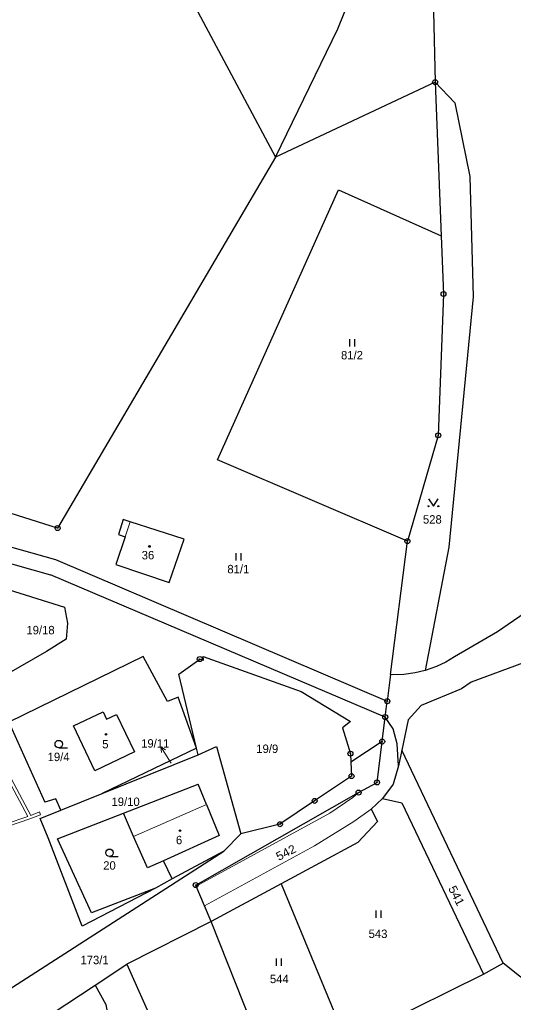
# Model space of a CAD drawing. Extents: x -653193 to -651624, y -1092017 to -1090260.
# Drawn here: x -652659.4 to -652559.8, y -1091313.6 to -1091115.4 of the extents above; entities that cross this region are included whole.
import ezdxf
from ezdxf.enums import TextEntityAlignment as Align

# ---------------------------------------------------------------- set-up
doc = ezdxf.new("R2010")
doc.units = 0
doc.header["$LTSCALE"] = 0.68
for name, color, linetype, lineweight in [('1', 7, 'Continuous', 25), ('13', 7, 'Continuous', 13), ('3', 7, 'Continuous', 25), ('4', 7, 'Continuous', 13), ('5', 7, 'Continuous', 25), ('7', 7, 'Continuous', 13), ('8', 7, 'Continuous', 25)]:
    doc.layers.add(name, color=color, linetype=linetype, lineweight=lineweight)
doc.layers.add('2', color=7, linetype='Continuous')

msp = doc.modelspace()

# ---------------------------------------------------------------- linework, layer by layer
at = {"layer": '1'}
for p, q in [((-652699, -1090972.63), (-652607.81, -1091143.07)), ((-652595.19, -1091117.19), (-652566.54, -1091045.56)), ((-652575.91, -1091113.74), (-652575.59, -1091127.97)), ((-652607.81, -1091143.07), (-652595.19, -1091117.19)), ((-652575.59, -1091127.97), (-652607.81, -1091143.07)), ((-652575.59, -1091127.97), (-652571.62, -1091132.16)), ((-652575.59, -1091127.97), (-652574.36, -1091158.97)), ((-652571.62, -1091132.16), (-652568.59, -1091146.97)), ((-652607.81, -1091143.07), (-652651.78, -1091217.9)), ((-652568.59, -1091146.97), (-652567.93, -1091171.28)), ((-652619.54, -1091204.12), (-652595.12, -1091149.69)), ((-652595.12, -1091149.69), (-652574.36, -1091158.97)), ((-652574.36, -1091158.97), (-652573.9, -1091170.7)), ((-652573.9, -1091170.7), (-652574.96, -1091199.2)), ((-652567.93, -1091171.28), (-652572.82, -1091221.74)), ((-652651.78, -1091217.9), (-652718.72, -1091196.81)), ((-652740.73, -1091199.19), (-652652.24, -1091224.26)), ((-652574.96, -1091199.2), (-652581.18, -1091220.54)), ((-652742.73, -1091201.93), (-652653.19, -1091227.34)), ((-652581.18, -1091220.54), (-652619.54, -1091204.12)), ((-652638.54, -1091216.14), (-652639.52, -1091219.18)), ((-652637.11, -1091216.61), (-652638.54, -1091216.14)), ((-652626.27, -1091220.15), (-652637.11, -1091216.61)), ((-652638.14, -1091219.64), (-652640.05, -1091225.25)), ((-652639.52, -1091219.18), (-652638.14, -1091219.64)), ((-652584.56, -1091247.44), (-652581.18, -1091220.54)), ((-652572.82, -1091221.74), (-652577.62, -1091246.64)), ((-652652.24, -1091224.26), (-652585.24, -1091252.83)), ((-652540.35, -1091223.27), (-652563.01, -1091238.81)), ((-652676.04, -1091225.83), (-652650.37, -1091233.85)), ((-652585.65, -1091256.02), (-652653.19, -1091227.34)), ((-652650.37, -1091233.85), (-652649.81, -1091237.05)), ((-652649.81, -1091237.05), (-652650.07, -1091240.31)), ((-652650.07, -1091240.31), (-652654.03, -1091242.76)), ((-652563.01, -1091238.81), (-652571.65, -1091243.87)), ((-652654.03, -1091242.76), (-652662.13, -1091247.41)), ((-652634.48, -1091243.82), (-652661.64, -1091257.02)), ((-652629.57, -1091252.89), (-652634.48, -1091243.82)), ((-652627.33, -1091247.39), (-652623.09, -1091244.32)), ((-652623.09, -1091244.32), (-652622.32, -1091244.57)), ((-652622.32, -1091244.57), (-652622.43, -1091243.83)), ((-652622.43, -1091243.83), (-652602.63, -1091250.88)), ((-652571.65, -1091243.87), (-652573.45, -1091244.94)), ((-652575.34, -1091245.82), (-652577.62, -1091246.64)), ((-652573.45, -1091244.94), (-652575.34, -1091245.82)), ((-652557.72, -1091245.07), (-652568.28, -1091248.96)), ((-652623.76, -1091262.29), (-652627.33, -1091247.39)), ((-652584.56, -1091247.44), (-652585.24, -1091252.83)), ((-652584.13, -1091247.52), (-652584.56, -1091247.44)), ((-652581.9, -1091247.44), (-652584.13, -1091247.52)), ((-652579.63, -1091247.12), (-652581.9, -1091247.44)), ((-652577.62, -1091246.64), (-652579.63, -1091247.12)), ((-652570.26, -1091250.29), (-652578.42, -1091253.66)), ((-652568.28, -1091248.96), (-652570.26, -1091250.29)), ((-652627.46, -1091251.99), (-652629.57, -1091252.89)), ((-652623.76, -1091262.29), (-652627.46, -1091251.99)), ((-652602.63, -1091250.88), (-652592.67, -1091256.93)), ((-652585.65, -1091256.02), (-652585.24, -1091252.83)), ((-652578.42, -1091253.66), (-652581.03, -1091256.58)), ((-652648.56, -1091257.78), (-652642.62, -1091254.96)), ((-652642.62, -1091254.96), (-652641.91, -1091256.46)), ((-652641.91, -1091256.46), (-652639.87, -1091255.49)), ((-652639.87, -1091255.49), (-652636.29, -1091263.04)), ((-652586.27, -1091260.95), (-652585.65, -1091256.02)), ((-652584.03, -1091258.36), (-652585.65, -1091256.02)), ((-652661.64, -1091257.02), (-652654.35, -1091273.21)), ((-652644.26, -1091266.83), (-652648.56, -1091257.78)), ((-652592.67, -1091256.93), (-652594.3, -1091258.2)), ((-652594.3, -1091258.2), (-652592.68, -1091263.4)), ((-652583.23, -1091261.42), (-652584.03, -1091258.36)), ((-652581.03, -1091256.58), (-652582.33, -1091262.72)), ((-652623.76, -1091262.29), (-652642.77, -1091271.41)), ((-652623.43, -1091263.65), (-652623.76, -1091262.29)), ((-652623.43, -1091263.65), (-652619.72, -1091261.95)), ((-652619.72, -1091261.95), (-652614.79, -1091279.58)), ((-652586.27, -1091260.95), (-652592.6, -1091265.08)), ((-652587.31, -1091269.19), (-652586.27, -1091260.95)), ((-652583, -1091265.88), (-652583.23, -1091261.42)), ((-652636.29, -1091263.04), (-652644.26, -1091266.83)), ((-652642.77, -1091271.41), (-652623.43, -1091263.65)), ((-652592.68, -1091263.4), (-652592.6, -1091265.08)), ((-652582.33, -1091262.72), (-652583, -1091265.88)), ((-652561.87, -1091305.65), (-652582.33, -1091262.72)), ((-652592.6, -1091265.08), (-652592.45, -1091267.92)), ((-652583, -1091265.88), (-652584.07, -1091269.52)), ((-652592.45, -1091267.92), (-652599.9, -1091272.92)), ((-652621.72, -1091273.68), (-652623.38, -1091269.58)), ((-652591.03, -1091271.25), (-652587.31, -1091269.19)), ((-652584.07, -1091269.52), (-652586.24, -1091272.47)), ((-652651.12, -1091274.76), (-652642.77, -1091271.41)), ((-652623.91, -1091289.9), (-652591.03, -1091271.25)), ((-652652.13, -1091272.54), (-652654.35, -1091273.21)), ((-652651.12, -1091274.76), (-652652.13, -1091272.54)), ((-652621.72, -1091273.68), (-652619.16, -1091279.89)), ((-652599.9, -1091272.92), (-652606.9, -1091277.63)), ((-652586.24, -1091272.47), (-652588.5, -1091274.56)), ((-652586.24, -1091272.47), (-652582.31, -1091273.31)), ((-652582.31, -1091273.31), (-652565.79, -1091307.87)), ((-652655.33, -1091276.44), (-652651.12, -1091274.76)), ((-652636.46, -1091280.08), (-652638.49, -1091275.43)), ((-652588.5, -1091274.56), (-652587.21, -1091277.07)), ((-652653.7, -1091280.37), (-652655.33, -1091276.44)), ((-652606.9, -1091277.63), (-652614.79, -1091279.58)), ((-652587.21, -1091277.07), (-652591.18, -1091281.29)), ((-652633.64, -1091286.45), (-652636.46, -1091280.08)), ((-652619.16, -1091279.89), (-652630.42, -1091284.99)), ((-652614.79, -1091279.58), (-652618.24, -1091283.07)), ((-652646.81, -1091298.16), (-652653.7, -1091280.37)), ((-652644.97, -1091295.52), (-652651.79, -1091280.58)), ((-652591.18, -1091281.29), (-652606.63, -1091289.65)), ((-652675.52, -1091319.87), (-652618.24, -1091283.07)), ((-652618.24, -1091283.07), (-652628.63, -1091288.66)), ((-652630.42, -1091284.99), (-652633.64, -1091286.45)), ((-652628.63, -1091288.66), (-652630.42, -1091284.99)), ((-652628.63, -1091288.66), (-652632.03, -1091290.49)), ((-652623.81, -1091290.15), (-652623.91, -1091289.9)), ((-652606.63, -1091289.65), (-652620.82, -1091297.26)), ((-652606.63, -1091289.65), (-652593.47, -1091321.5)), ((-652632.03, -1091290.49), (-652646.81, -1091298.16)), ((-652632.03, -1091290.49), (-652644.97, -1091295.52)), ((-652622.15, -1091294.08), (-652623.81, -1091290.15)), ((-652620.82, -1091297.26), (-652622.15, -1091294.08)), ((-652620.82, -1091297.26), (-652637.81, -1091305.85)), ((-652610.54, -1091322.98), (-652620.82, -1091297.26)), ((-652644.23, -1091310.07), (-652637.81, -1091305.85)), ((-652637.81, -1091305.85), (-652624.61, -1091335.43)), ((-652565.79, -1091307.87), (-652561.87, -1091305.65)), ((-652515.29, -1091342.68), (-652561.87, -1091305.65)), ((-652593.47, -1091321.5), (-652565.79, -1091307.87)), ((-652652.89, -1091315.8), (-652644.23, -1091310.07))]:
    msp.add_line(p, q, dxfattribs=at)
for points in [[(-652640.05, -1091225.25), (-652629.26, -1091228.87), (-652626.27, -1091220.15)], [(-652651.79, -1091280.58), (-652638.49, -1091275.43), (-652623.38, -1091269.58)], [(-652644.23, -1091310.07), (-652642.03, -1091313.97), (-652638.43, -1091334.25)]]:
    msp.add_lwpolyline(points, dxfattribs=at)
at = {"layer": '13'}
for points in [[(-652661.68, -1091268.72), (-652657.77, -1091276.05), (-652662.16, -1091277.55)], [(-652661.92, -1091278.11), (-652657.42, -1091276.56), (-652655.22, -1091275.71), (-652655.45, -1091275.14), (-652657.2, -1091275.85), (-652661.16, -1091268.42)]]:
    msp.add_lwpolyline(points, dxfattribs=at)
at = {"layer": '3'}
for p, q in [((-652592.811, -1091181.28), (-652592.811, -1091179.78)), ((-652591.81, -1091181.28), (-652591.81, -1091179.78)), ((-652615.761, -1091224.45), (-652615.761, -1091222.95)), ((-652614.76, -1091224.45), (-652614.76, -1091222.95)), ((-652651.553, -1091262.21), (-652649.803, -1091262.21)), ((-652641.313, -1091284.13), (-652639.563, -1091284.13)), ((-652587.471, -1091296.5), (-652587.471, -1091295)), ((-652586.47, -1091296.5), (-652586.47, -1091295)), ((-652607.571, -1091306.19), (-652607.571, -1091304.69)), ((-652606.57, -1091306.19), (-652606.57, -1091304.69))]:
    msp.add_line(p, q, dxfattribs=at)
msp.add_lwpolyline([(-652576.94, -1091211.989), (-652575.94, -1091213.49), (-652574.94, -1091211.989)], dxfattribs=at)
for centre, radius in [((-652576.94, -1091213.4895), 0.1), ((-652574.94, -1091213.4895), 0.1), ((-652651.5529, -1091261.4598), 0.75), ((-652641.3129, -1091283.3798), 0.75)]:
    msp.add_circle(centre, radius, dxfattribs=at)
at = {"layer": '4'}
for p, q in [((-652638.14, -1091219.64), (-652637.11, -1091216.61)), ((-652596.81, -1091275.39), (-652592.18, -1091272.27)), ((-652592.18, -1091272.27), (-652591.03, -1091271.25)), ((-652636.46, -1091280.08), (-652621.72, -1091273.68)), ((-652623.81, -1091290.15), (-652596.81, -1091275.39)), ((-652592, -1091277.1), (-652588.5, -1091274.56)), ((-652599.96, -1091281.99), (-652592, -1091277.1)), ((-652622.15, -1091294.08), (-652599.96, -1091281.99))]:
    msp.add_line(p, q, dxfattribs=at)
at = {"layer": '5'}
for centre in [(-652633.2568, -1091221.6092), (-652642.0168, -1091259.4992), (-652627.0868, -1091278.9192)]:
    msp.add_circle(centre, 0.175, dxfattribs=at)
at = {"layer": '7'}
msp.add_line((-652630.94, -1091262.015), (-652630.834, -1091263.13), dxfattribs=at)
msp.add_lwpolyline([(-652628.89, -1091265.3), (-652629.35, -1091264.56), (-652630.94, -1091262.015), (-652629.985, -1091262.599)], dxfattribs=at)
at = {"layer": '8'}
for centre, radius in [((-652575.59, -1091127.9699), 0.5), ((-652575.59, -1091127.9699), 0.0303), ((-652573.9, -1091170.6999), 0.5), ((-652573.9, -1091170.6999), 0.0303), ((-652574.96, -1091199.1999), 0.5), ((-652574.96, -1091199.1999), 0.0303), ((-652651.78, -1091217.8999), 0.5), ((-652651.78, -1091217.8999), 0.0303), ((-652581.18, -1091220.5399), 0.5), ((-652581.18, -1091220.5399), 0.0303), ((-652623.09, -1091244.3199), 0.5), ((-652623.09, -1091244.3199), 0.0303), ((-652585.24, -1091252.8299), 0.5), ((-652585.24, -1091252.8299), 0.0303), ((-652585.65, -1091256.0199), 0.5), ((-652585.65, -1091256.0199), 0.0303), ((-652586.27, -1091260.9499), 0.5), ((-652586.27, -1091260.9499), 0.0303), ((-652592.68, -1091263.3999), 0.5), ((-652592.68, -1091263.3999), 0.0303), ((-652592.45, -1091267.9199), 0.5), ((-652592.45, -1091267.9199), 0.0303), ((-652587.31, -1091269.1899), 0.5), ((-652587.31, -1091269.1899), 0.0303), ((-652591.03, -1091271.2499), 0.5), ((-652591.03, -1091271.2499), 0.0303), ((-652599.9, -1091272.9199), 0.5), ((-652599.9, -1091272.9199), 0.0303), ((-652606.9, -1091277.6299), 0.5), ((-652606.9, -1091277.6299), 0.0303), ((-652623.91, -1091289.8999), 0.5), ((-652623.91, -1091289.8999), 0.0303)]:
    msp.add_circle(centre, radius, dxfattribs=at)

# ---------------------------------------------------------------- texts
at = {"layer": '2'}
for s, p in [('81/2', (-652592.369, -1091183.885)), ('528', (-652576.149, -1091217.005)), ('36', (-652633.549, -1091224.215)), ('81/1', (-652615.309, -1091227.025)), ('19/18', (-652655.23, -1091239.325)), ('5', (-652642.14, -1091262.325)), ('19/9', (-652609.469, -1091263.255)), ('19/4', (-652651.579, -1091264.895)), ('19/10', (-652638.06, -1091273.945)), ('6', (-652627.27, -1091281.665)), ('20', (-652641.319, -1091286.795)), ('543', (-652587.109, -1091300.575)), ('173/1', (-652644.32, -1091305.855)), ('544', (-652607.029, -1091309.675))]:
    msp.add_text(s, height=1.7, dxfattribs=at).set_placement(p, align=Align.CENTER)
msp.add_text('19/11', height=1.7, dxfattribs=at).set_placement((-652629.23, -1091262.175), align=Align.RIGHT)
at = {"layer": '2', "width": 1.1}
for s, rotation, p in [('542', 27, (-652605.3094, -1091284.0983)), ('541', 297, (-652572.0383, -1091292.4196))]:
    msp.add_text(s, height=1.7, rotation=rotation, dxfattribs=at).set_placement(p, align=Align.CENTER)

doc.saveas('drawing.dxf')
